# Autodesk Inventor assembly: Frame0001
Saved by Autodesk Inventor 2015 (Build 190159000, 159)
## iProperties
Created: 2015-05
Part Number: Frame0001
Document SubType Name: Assembly
Designer: TREINA6
_FrameDoc: Frame Assembly
_Version: 15.0.0
Author: TREINA6
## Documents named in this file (68)
- C:\Users\TREINA6\Desktop\#46- Sheet Metal Technology\WSC2015_TP46_pre\Sheet Metal\Base Assembly\Base Frame\Base Frame\Frame\Frame0001.iam
- C:\Users\TREINA6\Desktop\#46- Sheet Metal Technology\WSC2015_TP46_pre\Sheet Metal\Base Assembly\Base Frame\Base Frame\Frame\Skeleton0001.ipt
- C:\Users\TREINA6\Desktop\#46- Sheet Metal Technology\WSC2015_TP46_pre\Sheet Metal\Base Assembly\Base Frame\Base Frame\Frame\DIN 20 x 20 x 2 00000001.ipt
- DIN 20 x 20 x 2 00000001.ipt
- C:\Users\TREINA6\Desktop\#46- Sheet Metal Technology\WSC2015_TP46_pre\Sheet Metal\Base Assembly\Base Frame\Base Frame\Frame\DIN 20 x 20 x 2 00000002.ipt
- DIN 20 x 20 x 2 00000002.ipt
- C:\Users\TREINA6\Desktop\#46- Sheet Metal Technology\WSC2015_TP46_pre\Sheet Metal\Base Assembly\Base Frame\Base Frame\Frame\DIN 20 x 20 x 2 00000003.ipt
- DIN 20 x 20 x 2 00000003.ipt
- C:\Users\TREINA6\Desktop\#46- Sheet Metal Technology\WSC2015_TP46_pre\Sheet Metal\Base Assembly\Base Frame\Base Frame\Frame\DIN 20 x 20 x 2 00000004.ipt
- DIN 20 x 20 x 2 00000004.ipt
- C:\Users\TREINA6\Desktop\#46- Sheet Metal Technology\WSC2015_TP46_pre\Sheet Metal\Base Assembly\Base Frame\Base Frame\Frame\DIN 20 x 20 x 2 00000005.ipt
- DIN 20 x 20 x 2 00000005.ipt
- C:\Users\TREINA6\Desktop\#46- Sheet Metal Technology\WSC2015_TP46_pre\Sheet Metal\Base Assembly\Base Frame\Base Frame\Frame\DIN 20 x 20 x 2 00000006.ipt
- DIN 20 x 20 x 2 00000006.ipt
- C:\Users\TREINA6\Desktop\#46- Sheet Metal Technology\WSC2015_TP46_pre\Sheet Metal\Base Assembly\Base Frame\Base Frame\Frame\DIN 20 x 20 x 2 00000007.ipt
- DIN 20 x 20 x 2 00000007.ipt
- C:\Users\TREINA6\Desktop\#46- Sheet Metal Technology\WSC2015_TP46_pre\Sheet Metal\Base Assembly\Base Frame\Base Frame\Frame\DIN 20 x 20 x 2 00000008.ipt
- DIN 20 x 20 x 2 00000008.ipt
- C:\Users\TREINA6\Desktop\#46- Sheet Metal Technology\WSC2015_TP46_pre\Sheet Metal\Base Assembly\Base Frame\Base Frame\Frame\DIN 20 x 20 x 2 00000009.ipt
- DIN 20 x 20 x 2 00000009.ipt
- C:\Users\TREINA6\Desktop\#46- Sheet Metal Technology\WSC2015_TP46_pre\Sheet Metal\Base Assembly\Base Frame\Base Frame\Frame\DIN 20 x 20 x 2 00000010.ipt
- DIN 20 x 20 x 2 00000010.ipt
- C:\Users\TREINA6\Desktop\#46- Sheet Metal Technology\WSC2015_TP46_pre\Sheet Metal\Base Assembly\Base Frame\Base Frame\Frame\DIN 20 x 20 x 2 00000011.ipt
- DIN 20 x 20 x 2 00000011.ipt
- C:\Users\TREINA6\Desktop\#46- Sheet Metal Technology\WSC2015_TP46_pre\Sheet Metal\Base Assembly\Base Frame\Base Frame\Frame\DIN 20 x 20 x 2 00000012.ipt
- DIN 20 x 20 x 2 00000012.ipt
- C:\Users\TREINA6\Desktop\#46- Sheet Metal Technology\WSC2015_TP46_pre\Sheet Metal\Base Assembly\Base Frame\Base Frame\Frame\DIN 20 x 20 x 2 00000013.ipt
- DIN 20 x 20 x 2 00000013.ipt
- C:\Users\TREINA6\Desktop\#46- Sheet Metal Technology\WSC2015_TP46_pre\Sheet Metal\Base Assembly\Base Frame\Base Frame\Frame\DIN 20 x 20 x 2 00000014.ipt
- DIN 20 x 20 x 2 00000014.ipt
- C:\Users\TREINA6\Desktop\#46- Sheet Metal Technology\WSC2015_TP46_pre\Sheet Metal\Base Assembly\Base Frame\Base Frame\Frame\DIN 20 x 20 x 2 00000015.ipt
- DIN 20 x 20 x 2 00000015.ipt
- C:\Users\TREINA6\Desktop\#46- Sheet Metal Technology\WSC2015_TP46_pre\Sheet Metal\Base Assembly\Base Frame\Base Frame\Frame\DIN 20 x 20 x 2 00000016.ipt
- DIN 20 x 20 x 2 00000016.ipt
- C:\Users\TREINA6\Desktop\#46- Sheet Metal Technology\WSC2015_TP46_pre\Sheet Metal\Base Assembly\Base Frame\Base Frame\Frame\DIN 20 x 20 x 2 00000017.ipt
- DIN 20 x 20 x 2 00000017.ipt
- C:\Users\TREINA6\Desktop\#46- Sheet Metal Technology\WSC2015_TP46_pre\Sheet Metal\Base Assembly\Base Frame\Base Frame\Frame\DIN 20 x 20 x 2 00000018.ipt
- DIN 20 x 20 x 2 00000018.ipt
- C:\Users\TREINA6\Desktop\#46- Sheet Metal Technology\WSC2015_TP46_pre\Sheet Metal\Base Assembly\Base Frame\Base Frame\Frame\DIN 20 x 20 x 2 00000019.ipt
- DIN 20 x 20 x 2 00000019.ipt
- C:\Users\TREINA6\Desktop\#46- Sheet Metal Technology\WSC2015_TP46_pre\Sheet Metal\Base Assembly\Base Frame\Base Frame\Frame\DIN 20 x 20 x 2 00000020.ipt
- DIN 20 x 20 x 2 00000020.ipt
- C:\Users\TREINA6\Desktop\#46- Sheet Metal Technology\WSC2015_TP46_pre\Sheet Metal\Base Assembly\Base Frame\Base Frame\Frame\DIN 20 x 20 x 2 00000021.ipt
- DIN 20 x 20 x 2 00000021.ipt
- C:\Users\TREINA6\Desktop\#46- Sheet Metal Technology\WSC2015_TP46_pre\Sheet Metal\Base Assembly\Base Frame\Base Frame\Frame\DIN 20 x 20 x 2 00000022.ipt
- DIN 20 x 20 x 2 00000022.ipt
- C:\Users\TREINA6\Desktop\#46- Sheet Metal Technology\WSC2015_TP46_pre\Sheet Metal\Base Assembly\Base Frame\Base Frame\Frame\DIN 20 x 20 x 2 00000023.ipt
- DIN 20 x 20 x 2 00000023.ipt
- C:\Users\TREINA6\Desktop\#46- Sheet Metal Technology\WSC2015_TP46_pre\Sheet Metal\Base Assembly\Base Frame\Base Frame\Frame\DIN 20 x 20 x 2 00000024.ipt
- DIN 20 x 20 x 2 00000024.ipt
- C:\Users\TREINA6\Desktop\#46- Sheet Metal Technology\WSC2015_TP46_pre\Sheet Metal\Base Assembly\Base Frame\Base Frame\Frame\DIN 20 x 20 x 2 00000025.ipt
- DIN 20 x 20 x 2 00000025.ipt
- C:\Users\TREINA6\Desktop\#46- Sheet Metal Technology\WSC2015_TP46_pre\Sheet Metal\Base Assembly\Base Frame\Base Frame\Frame\DIN 20 x 20 x 2 00000026.ipt
- DIN 20 x 20 x 2 00000026.ipt
- C:\Users\TREINA6\Desktop\#46- Sheet Metal Technology\WSC2015_TP46_pre\Sheet Metal\Base Assembly\Base Frame\Base Frame\Frame\DIN 20 x 20 x 2 00000027.ipt
- DIN 20 x 20 x 2 00000027.ipt
- C:\Users\TREINA6\Desktop\#46- Sheet Metal Technology\WSC2015_TP46_pre\Sheet Metal\Base Assembly\Base Frame\Base Frame\Frame\DIN 20 x 20 x 2 00000028.ipt
- DIN 20 x 20 x 2 00000028.ipt
- C:\Users\TREINA6\Desktop\#46- Sheet Metal Technology\WSC2015_TP46_pre\Sheet Metal\Base Assembly\Base Frame\Base Frame\Frame\DIN 20 x 20 x 2 00000029.ipt
- DIN 20 x 20 x 2 00000029.ipt
- C:\Users\TREINA6\Desktop\#46- Sheet Metal Technology\WSC2015_TP46_pre\Sheet Metal\Base Assembly\Base Frame\Base Frame\Frame\DIN 20 x 20 x 2 00000030.ipt
- DIN 20 x 20 x 2 00000030.ipt
- C:\Users\TREINA6\Desktop\#46- Sheet Metal Technology\WSC2015_TP46_pre\Sheet Metal\Base Assembly\Base Frame\Base Frame\Frame\DIN 20 x 20 x 2 00000031.ipt
- DIN 20 x 20 x 2 00000031.ipt
- C:\Users\TREINA6\Desktop\#46- Sheet Metal Technology\WSC2015_TP46_pre\Sheet Metal\Base Assembly\Base Frame\Base Frame\Frame\DIN 20 x 20 x 2 00000032.ipt
- DIN 20 x 20 x 2 00000032.ipt
- C:\Users\TREINA6\Desktop\#46- Sheet Metal Technology\WSC2015_TP46_pre\Sheet Metal\Base Assembly\Base Frame\Base Frame\Frame\DIN 20 x 20 x 2 00000033.ipt
- DIN 20 x 20 x 2 00000033.ipt
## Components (34 placed, 34 different names)
1. Frame Reference Model
2. DIN 20 x 20 x 2 00000001:1
3. DIN 20 x 20 x 2 00000002:1
4. DIN 20 x 20 x 2 00000003:1
5. DIN 20 x 20 x 2 00000004:1
6. DIN 20 x 20 x 2 00000005:1
7. DIN 20 x 20 x 2 00000006:1
8. DIN 20 x 20 x 2 00000007:1
9. DIN 20 x 20 x 2 00000008:1
10. DIN 20 x 20 x 2 00000009:1
11. DIN 20 x 20 x 2 00000010:1
12. DIN 20 x 20 x 2 00000011:1
13. DIN 20 x 20 x 2 00000012:1
14. DIN 20 x 20 x 2 00000013:1
15. DIN 20 x 20 x 2 00000014:1
16. DIN 20 x 20 x 2 00000015:1
17. DIN 20 x 20 x 2 00000016:1
18. DIN 20 x 20 x 2 00000017:1
19. DIN 20 x 20 x 2 00000018:1
20. DIN 20 x 20 x 2 00000019:1
21. DIN 20 x 20 x 2 00000020:1
22. DIN 20 x 20 x 2 00000021:1
23. DIN 20 x 20 x 2 00000022:1
24. DIN 20 x 20 x 2 00000023:1
25. DIN 20 x 20 x 2 00000024:1
26. DIN 20 x 20 x 2 00000025:1
27. DIN 20 x 20 x 2 00000026:1
28. DIN 20 x 20 x 2 00000027:1
29. DIN 20 x 20 x 2 00000028:1
30. DIN 20 x 20 x 2 00000029:1
31. DIN 20 x 20 x 2 00000030:1
32. DIN 20 x 20 x 2 00000031:1
33. DIN 20 x 20 x 2 00000032:1
34. DIN 20 x 20 x 2 00000033:1
